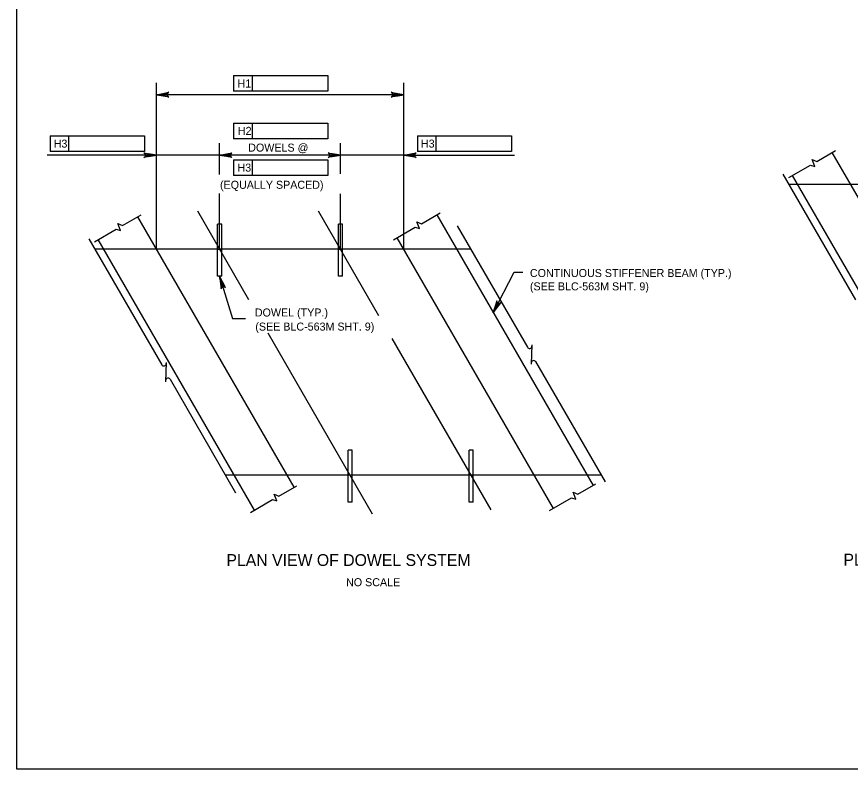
# Model space of a CAD drawing. Extents: x 638268 to 640277, y 295465 to 298435.
# Drawn here: x 639316.5 to 639628.9, y 296668.5 to 296950.5 of the extents above; entities that cross this region are included whole.
import ezdxf

# ---------------------------------------------------------------- set-up
doc = ezdxf.new("R2010")
doc.units = 0
for name, color, linetype in [('2', 7, 'Continuous'), ('3', 7, 'Continuous'), ('4', 7, 'Continuous')]:
    doc.layers.add(name, color=color, linetype=linetype)

# ---------------------------------------------------------------- blocks, each defined once
blk = doc.blocks.new('D')
at = {"layer": '3'}
for p, q in [((-0.48575, 0.574125), (-0.574125, 0.48575)), ((0.6115, -0.52325), (-0.48575, 0.574125)), ((0.52325, -0.6115), (-0.574125, 0.48575)), ((0.6115, -0.52325), (0.52325, -0.6115))]:
    blk.add_line(p, q, dxfattribs=at)

msp = doc.modelspace()

# ---------------------------------------------------------------- linework, layer by layer
at = {"layer": '2'}
for p, q in [((639316.46, 296668.46), (639316.46, 297232.46)), ((639787.93, 296887.61), (639605.87, 296887.61)), ((639486.62, 296863.32), (639345.79, 296863.32)), ((639535.58, 296778.61), (639394.75, 296778.61)), ((640102.46, 296668.46), (639316.46, 296668.46))]:
    msp.add_line(p, q, dxfattribs=at)
at = {"layer": '3'}
for p, q in [((639616.36, 296896.24), (639623.37, 296900.29)), ((639622.02, 296899.51), (639680.61, 296798.15)), ((639615.57, 296894.38), (639614.56, 296896.98)), ((639614.56, 296896.98), (639616.36, 296896.24)), ((639605.86, 296890.17), (639614.02, 296894.88)), ((639614.02, 296894.88), (639615.57, 296894.38)), ((639603.62, 296891.5), (639630.89, 296844.33)), ((639665.78, 296789.58), (639607.2, 296890.94)), ((639403.47, 296844.37), (639384.3, 296877.54)), ((639452.22, 296838.41), (639429.61, 296877.54)), ((639356.12, 296872.22), (639363.13, 296876.27)), ((639361.78, 296875.49), (639420.37, 296774.13)), ((639468.2, 296872.89), (639475.21, 296876.95)), ((639473.86, 296876.16), (639532.45, 296774.81)), ((639355.33, 296870.36), (639354.32, 296872.96)), ((639354.32, 296872.96), (639356.12, 296872.22)), ((639457.7, 296866.82), (639465.86, 296871.54)), ((639465.86, 296871.54), (639467.41, 296871.03)), ((639466.4, 296873.63), (639468.2, 296872.89)), ((639467.41, 296871.03), (639466.4, 296873.63)), ((639481.56, 296872.08), (639507.85, 296826.59)), ((639345.62, 296866.15), (639353.78, 296870.86)), ((639353.78, 296870.86), (639355.33, 296870.36)), ((639343.54, 296867.21), (639370.81, 296820.04)), ((639405.54, 296765.56), (639346.96, 296866.92)), ((639517.62, 296766.24), (639459.03, 296867.59)), ((639391.71, 296863.32), (639393.28, 296863.32)), ((639437.03, 296863.32), (639438.6, 296863.32)), ((639449.85, 296764.08), (639410.7, 296831.85)), ((639494.27, 296765.64), (639457.16, 296829.86)), ((639509.56, 296827.5), (639509.29, 296820.23)), ((639510.96, 296821.21), (639537.02, 296776.13)), ((639372.52, 296820.94), (639372.25, 296813.68)), ((639373.92, 296814.66), (639398.51, 296772.1)), ((639414.71, 296770.86), (639421.4, 296774.73)), ((639526.79, 296771.53), (639533.48, 296775.4)), ((639412.91, 296771.6), (639414.71, 296770.86)), ((639413.92, 296769), (639412.91, 296771.6)), ((639524.99, 296772.27), (639526.79, 296771.53)), ((639526, 296769.67), (639524.99, 296772.27)), ((639404.05, 296764.7), (639412.37, 296769.51)), ((639412.37, 296769.51), (639413.92, 296769)), ((639516.12, 296765.37), (639524.45, 296770.18)), ((639524.45, 296770.18), (639526, 296769.67))]:
    msp.add_line(p, q, dxfattribs=at)
for centre, start, end in [((639508.64, 296827.05), 210.0292, 0.0292), ((639510.22, 296820.69), 35.3578, 177.8964), ((639371.59, 296820.49), 210.0292, 0.0292), ((639373.18, 296814.13), 35.3578, 177.8964)]:
    msp.add_arc(centre, 0.909, start, end, dxfattribs=at)
at = {"layer": '4'}
for p, q in [((639397.77, 296928.46), (639433.08, 296928.46)), ((639397.77, 296928.46), (639397.77, 296922.56)), ((639404.66, 296928.46), (639404.66, 296922.56)), ((639433.08, 296928.46), (639433.08, 296922.56)), ((639368.82, 296864.88), (639368.82, 296925.73)), ((639461.51, 296864.88), (639461.51, 296925.73)), ((639461.51, 296921.23), (639368.82, 296921.23)), ((639433.08, 296922.56), (639397.77, 296922.56)), ((639397.77, 296910.59), (639397.77, 296904.68)), ((639397.77, 296910.59), (639433.08, 296910.59)), ((639404.66, 296910.59), (639404.66, 296904.68)), ((639433.08, 296910.59), (639433.08, 296904.68)), ((639329, 296905.79), (639364.3, 296905.79)), ((639329, 296905.79), (639329, 296899.89)), ((639335.89, 296905.79), (639335.89, 296899.89)), ((639364.3, 296905.79), (639364.3, 296899.89)), ((639466.63, 296905.79), (639501.93, 296905.79)), ((639466.63, 296905.79), (639466.63, 296899.89)), ((639473.52, 296905.79), (639473.52, 296899.89)), ((639501.93, 296905.79), (639501.93, 296899.89)), ((639368.82, 296863.32), (639368.82, 296903.03)), ((639392.49, 296891.28), (639392.49, 296903.03)), ((639433.08, 296904.68), (639397.77, 296904.68)), ((639437.81, 296891.55), (639437.81, 296903.03)), ((639461.51, 296863.32), (639461.51, 296903.03)), ((639364.3, 296899.89), (639329, 296899.89)), ((639501.93, 296899.89), (639466.63, 296899.89)), ((639365.82, 296898.53), (639327.93, 296898.53)), ((639392.49, 296898.53), (639368.79, 296898.53)), ((639434.81, 296898.53), (639395.49, 296898.53)), ((639397.77, 296896.81), (639433.08, 296896.81)), ((639397.77, 296896.81), (639397.77, 296890.9)), ((639404.66, 296896.81), (639404.66, 296890.9)), ((639434.81, 296898.53), (639431.81, 296898.53)), ((639433.08, 296896.81), (639433.08, 296890.9)), ((639461.51, 296898.53), (639437.81, 296898.53)), ((639464.51, 296898.53), (639503.09, 296898.53)), ((639433.08, 296890.9), (639397.77, 296890.9)), ((639392.49, 296863.32), (639392.49, 296884.2)), ((639437.81, 296863.32), (639437.81, 296884.06)), ((639502.93, 296854.69), (639506.17, 296854.69)), ((639397.37, 296837.31), (639402.22, 296837.31))]:
    msp.add_line(p, q, dxfattribs=at)
for points in [[(639368.82, 296921.23), (639373.48, 296922.11), (639373.12, 296921.86), (639372.93, 296921.54), (639372.88, 296921.23), (639372.93, 296920.92), (639373.12, 296920.61), (639373.48, 296920.36), (639368.82, 296921.23), (639373.12, 296920.61), (639372.93, 296920.92), (639368.82, 296921.23), (639372.88, 296921.23), (639372.93, 296921.54), (639368.82, 296921.23), (639373.12, 296921.86)], [(639461.51, 296921.23), (639456.85, 296920.36), (639457.21, 296920.61), (639457.39, 296920.92), (639457.45, 296921.23), (639457.39, 296921.54), (639457.21, 296921.86), (639456.85, 296922.11), (639461.51, 296921.23), (639457.21, 296921.86), (639457.39, 296921.54), (639461.51, 296921.23), (639457.45, 296921.23), (639457.39, 296920.92), (639461.51, 296921.23), (639457.21, 296920.61)], [(639368.82, 296898.53), (639364.16, 296897.65), (639364.52, 296897.9), (639364.7, 296898.21), (639364.76, 296898.53), (639364.7, 296898.84), (639364.52, 296899.15), (639364.16, 296899.4), (639368.82, 296898.53), (639364.52, 296899.15), (639364.7, 296898.84), (639368.82, 296898.53), (639364.76, 296898.53), (639364.7, 296898.21), (639368.82, 296898.53), (639364.52, 296897.9)], [(639392.49, 296898.53), (639397.15, 296899.4), (639396.79, 296899.15), (639396.61, 296898.84), (639396.55, 296898.53), (639396.61, 296898.21), (639396.79, 296897.9), (639397.15, 296897.65), (639392.49, 296898.53), (639396.79, 296897.9), (639396.61, 296898.21), (639392.49, 296898.53), (639396.55, 296898.53), (639396.61, 296898.84), (639392.49, 296898.53), (639396.79, 296899.15)], [(639437.81, 296898.53), (639433.15, 296897.65), (639433.51, 296897.9), (639433.69, 296898.21), (639433.75, 296898.53), (639433.69, 296898.84), (639433.51, 296899.15), (639433.15, 296899.4), (639437.81, 296898.53), (639433.51, 296899.15), (639433.69, 296898.84), (639437.81, 296898.53), (639433.75, 296898.53), (639433.69, 296898.21), (639437.81, 296898.53), (639433.51, 296897.9)], [(639461.51, 296898.53), (639466.17, 296899.4), (639465.81, 296899.15), (639465.62, 296898.84), (639465.57, 296898.53), (639465.62, 296898.21), (639465.81, 296897.9), (639466.17, 296897.65), (639461.51, 296898.53), (639465.81, 296897.9), (639465.62, 296898.21), (639461.51, 296898.53), (639465.57, 296898.53), (639465.62, 296898.84), (639461.51, 296898.53), (639465.81, 296899.15)], [(639392.51, 296853.21), (639397.37, 296837.31)], [(639392.51, 296853.21), (639393.04, 296848.49), (639393.17, 296848.91), (639393.42, 296849.18), (639393.7, 296849.32), (639394.01, 296849.36), (639394.37, 296849.27), (639394.71, 296849), (639392.51, 296853.21), (639394.37, 296849.27), (639394.01, 296849.36), (639392.51, 296853.21), (639393.7, 296849.32), (639393.42, 296849.18), (639392.51, 296853.21), (639393.17, 296848.91)], [(639495.05, 296839.51), (639502.92, 296854.69)], [(639495.05, 296839.51), (639497.97, 296843.25), (639497.58, 296843.04), (639497.22, 296843.02), (639496.92, 296843.12), (639496.66, 296843.31), (639496.47, 296843.62), (639496.42, 296844.05), (639495.05, 296839.51), (639496.47, 296843.62), (639496.66, 296843.31), (639495.05, 296839.51), (639496.92, 296843.12), (639497.22, 296843.02), (639495.05, 296839.51), (639497.58, 296843.04)]]:
    msp.add_lwpolyline(points, dxfattribs=at)
for points in [[(639371.82, 296921.73), (639371.82, 296920.73), (639368.82, 296921.23)], [(639458.51, 296921.73), (639458.51, 296920.73), (639461.51, 296921.23)], [(639365.82, 296899.03), (639365.82, 296898.03), (639368.82, 296898.53)], [(639395.49, 296899.03), (639395.49, 296898.03), (639392.49, 296898.53)], [(639434.81, 296899.03), (639434.81, 296898.03), (639437.81, 296898.53)], [(639464.51, 296899.03), (639464.51, 296898.03), (639461.51, 296898.53)], [(639392.51, 296853.21), (639393.63, 296850.41), (639393.15, 296850.26)], [(639495.05, 296839.51), (639496.21, 296842.29), (639496.65, 296842.06)]]:
    msp.add_lwpolyline(points, close=True, dxfattribs=at)

# ---------------------------------------------------------------- block references
at = {"layer": '4', "xscale": 12.59905511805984, "yscale": 12.599055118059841, "rotation": -44.999951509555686}
for p in [(639392.5, 296863.32), (639437.82, 296863.32), (639441.46, 296778.61), (639486.78, 296778.61)]:
    msp.add_blockref('D', p, dxfattribs=at)

# ---------------------------------------------------------------- texts
at = {"layer": '4'}
for s, height, p in [('H1', 3, (639399.26, 296923.92)), ('H2', 3, (639399.36, 296906.18)), ('H3', 3, (639330.33, 296901.4)), ('DOWELS @', 3, (639403.23, 296899.9)), ('H3', 3, (639467.96, 296901.4)), ('H3', 3, (639399.22, 296892.4)), ('(EQUALLY SPACED)', 3, (639392.67, 296885.97)), ('CONTINUOUS STIFFENER BEAM (TYP.)', 3, (639508.81, 296852.91)), ('(SEE BLC-563M SHT. 9)', 3, (639508.81, 296847.91)), ('DOWEL (TYP.)', 3, (639405.72, 296838.12)), ('(SEE BLC-563M SHT. 9)', 3, (639405.9, 296832.84)), ('PLAN VIEW OF ALTERNATE INTERMEDIATE STIFFENER BEAM SYSTEM', 4.4292, (639626.31, 296744.8)), ('PLAN VIEW OF DOWEL SYSTEM', 4.4292, (639395.06, 296744.65)), ('NO SCALE', 3, (639439.91, 296737.06))]:
    msp.add_text(s, height=height, dxfattribs=at).set_placement(p)

doc.saveas('drawing.dxf')
